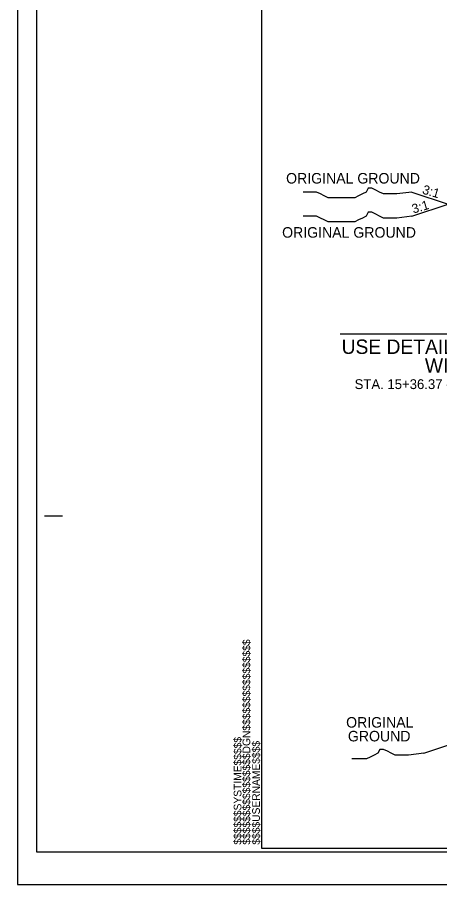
# Model space of a CAD drawing. Extents: x 2176156 to 2177167, y 76401 to 76644.
# Drawn here: x 2176629.3 to 2176675.5, y 76454.5 to 76549.5 of the extents above; entities that cross this region are included whole.
import ezdxf

# ---------------------------------------------------------------- set-up
doc = ezdxf.new("R2010")
doc.units = 0
for name, color, linetype in [('Exist Building Metal Canopy', 7, 'Continuous'), ('Exist Roads Curbs', 7, 'Continuous'), ('Exist Roads EOP Other', 7, 'Continuous'), ('Exist Structure Minor Culvert Topo', 7, 'Continuous'), ('Exist Vegetation Woods Line', 7, 'Continuous'), ('Model Boundary Lines Text', 7, 'Continuous'), ('Sheet Cutting Line CELL', 7, 'Continuous'), ('Sheet Data Field CELL', 7, 'Continuous'), ('Sheet Plot Border Outside CELL', 7, 'Continuous'), ('Sheet Sticker Exception Certification CELL', 7, 'Continuous')]:
    doc.layers.add(name, color=color, linetype=linetype)

msp = doc.modelspace()

# ---------------------------------------------------------------- linework, layer by layer
at = {"layer": 'Exist Roads Curbs'}
for points in [[(2176672.465, 76530.343), (2176670.795, 76530.135), (2176670.377, 76530.135), (2176669.75, 76530.135), (2176669.332, 76530.135), (2176668.914, 76530.343), (2176668.497, 76530.553), (2176668.079, 76530.763), (2176667.661, 76530.763), (2176667.452, 76530.343), (2176667.034, 76530.135), (2176666.616, 76529.926), (2176666.199, 76529.718), (2176665.781, 76529.718), (2176665.363, 76529.718), (2176664.946, 76529.718), (2176664.528, 76529.718), (2176664.11, 76529.718), (2176663.693, 76529.718), (2176663.275, 76529.718), (2176662.857, 76529.926), (2176662.44, 76530.135), (2176662.022, 76530.343), (2176661.395, 76530.343), (2176660.977, 76530.343), (2176660.56, 76530.343)], [(2176672.465, 76527.701), (2176670.795, 76527.493), (2176670.377, 76527.493), (2176669.75, 76527.493), (2176669.332, 76527.493), (2176668.914, 76527.701), (2176668.497, 76527.911), (2176668.079, 76528.12), (2176667.661, 76528.12), (2176667.452, 76527.701), (2176667.034, 76527.493), (2176666.616, 76527.283), (2176666.199, 76527.075), (2176665.781, 76527.075), (2176665.363, 76527.075), (2176664.946, 76527.075), (2176664.528, 76527.075), (2176664.11, 76527.075), (2176663.693, 76527.075), (2176663.275, 76527.075), (2176662.857, 76527.283), (2176662.44, 76527.493), (2176662.022, 76527.701), (2176661.395, 76527.701), (2176660.977, 76527.701), (2176660.56, 76527.701)], [(2176673.75, 76468.876), (2176672.079, 76468.668), (2176671.661, 76468.668), (2176671.034, 76468.668), (2176670.616, 76468.668), (2176670.199, 76468.876), (2176669.781, 76469.086), (2176669.363, 76469.295), (2176668.946, 76469.295), (2176668.736, 76468.876), (2176668.319, 76468.668), (2176667.901, 76468.458), (2176667.483, 76468.25), (2176667.066, 76468.25), (2176666.648, 76468.25), (2176666.23, 76468.25), (2176665.891, 76468.25)]]:
    msp.add_lwpolyline(points, dxfattribs=at)
at = {"layer": 'Exist Roads EOP Other'}
for p, q in [((2176672.465, 76530.343), (2176676.429, 76529.022)), ((2176672.465, 76527.701), (2176676.429, 76529.022)), ((2176673.75, 76468.876), (2176692.034, 76474.971))]:
    msp.add_line(p, q, dxfattribs=at)
at = {"layer": 'Model Boundary Lines Text'}
msp.add_line((2176664.598, 76514.814), (2176699.636, 76514.814), dxfattribs=at)
at = {"layer": 'Sheet Cutting Line CELL'}
msp.add_lwpolyline([(2176898.707, 76630.475), (2176629.267, 76630.475), (2176629.267, 76454.475), (2176898.707, 76454.475)], close=True, dxfattribs=at)
at = {"layer": 'Sheet Data Field CELL'}
for p, q in [((2176632.227, 76494.875), (2176634.227, 76494.875)), ((2176655.987, 76458.475), (2176655.987, 76458.475)), ((2176655.987, 76458.475), (2176655.987, 76458.475)), ((2176655.987, 76458.475), (2176655.987, 76458.475)), ((2176655.987, 76458.475), (2176655.987, 76458.475)), ((2176655.987, 76458.475), (2176655.987, 76458.475)), ((2176655.987, 76458.475), (2176655.987, 76458.475))]:
    msp.add_line(p, q, dxfattribs=at)
msp.add_lwpolyline([(2176895.987, 76626.475), (2176655.987, 76626.475), (2176655.987, 76458.475), (2176895.987, 76458.475)], close=True, dxfattribs=at)
msp.add_lwpolyline([(2176661.987, 76458.475), (2176661.987, 76458.475)], dxfattribs=at)
at = {"layer": 'Sheet Plot Border Outside CELL'}
msp.add_lwpolyline([(2176897.987, 76626.883), (2176631.347, 76626.883), (2176631.347, 76458.067), (2176897.987, 76458.067)], close=True, dxfattribs=at)
at = {"layer": 'Sheet Sticker Exception Certification CELL'}
for p, q in [((2176629.267, 76630.475), (2176629.267, 76454.475)), ((2176629.267, 76454.475), (2176898.707, 76454.475))]:
    msp.add_line(p, q, dxfattribs=at)

# ---------------------------------------------------------------- texts
at = {"layer": 'Exist Building Metal Canopy'}
for s, p in [('USE DETAIL D IN CONJUNCTION', (2176664.762, 76512.61)), ('WITH T.S. NO. 6', (2176673.884, 76510.543))]:
    msp.add_text(s, height=1.5766, rotation=0.00002, dxfattribs=at).set_placement(p)
at = {"layer": 'Exist Roads Curbs'}
for rotation, p in [(343.53506, (2176673.531, 76530.186)), (16.46494, (2176672.621, 76527.98))]:
    msp.add_text('3:1', height=1.0064, rotation=rotation, dxfattribs=at).set_placement(p)
at = {"layer": 'Exist Structure Minor Culvert Topo'}
for s, height, p in [('ORIGINAL GROUND', 1.15334, (2176658.687, 76531.273)), ('ORIGINAL GROUND', 1.15334, (2176658.251, 76525.344)), ('ORIGINAL', 1.1533, (2176665.259, 76471.678)), ('GROUND', 1.1533, (2176665.453, 76470.166))]:
    msp.add_text(s, height=height, dxfattribs=at).set_placement(p)
at = {"layer": 'Exist Vegetation Woods Line'}
msp.add_text('STA. 15+36.37 -Y4- TO STA. 17+39.90 -Y4-', height=1.0742, dxfattribs=at).set_placement((2176666.189, 76508.762))
at = {"layer": 'Sheet Data Field CELL'}
for s, p in [('$$$$$$$$$$$$$$$$DGN$$$$$$$$$$$$$$$$', (2176654.763, 76458.853)), ('$$$$$$SYSTIME$$$$$', (2176653.795, 76458.853)), ('$$$$USERNAME$$$$', (2176655.815, 76458.855))]:
    msp.add_text(s, height=0.84, rotation=90, dxfattribs=at).set_placement(p)

doc.saveas('drawing.dxf')
